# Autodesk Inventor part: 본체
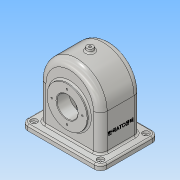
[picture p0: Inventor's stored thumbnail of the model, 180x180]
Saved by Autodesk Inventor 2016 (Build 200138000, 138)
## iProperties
Created: 2018-08
Part Number: 본체
Material: 알루미늄 6061
Document SubType Name: Modeling
Designer: Administrator
Density: 2.7 g/cm^3
Appearance: 알루미늄 - 평지
Mass: 1091.9 g
Surface Area: 1182.65 cm^2
Volume: 404.407 cm^3
Author: Administrator
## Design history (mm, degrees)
sketch "스케치1"
  geometry: L1 (-75, 55)-(75, 55); L2 (75, 55)-(75, -55); L3 (75, -55)-(-75, -55); L4 (-75, -55)-(-75, 55); L5 (-75, 55)-(75, -55); L6 (75, 55)-(-75, -55); 1 further point
  constraints: 12 end point, 2 midpoint, 2 parallel, 1 horizontal, 1 perpendicular
  dimensions: "d0" = 150 distance of L2.end L3.end; "d1" = 110 distance of L1.end L2.end
extrude "돌출1" new body sketch "스케치1" distance "d2" = 10; taper "d3" = 0 deg
sketch "스케치2"
  geometry: L1 (-75, 0)-(75, 0) reference; L2 (58, 78)-(58, 10); L3 (-75, 10)-(75, 10) reference; L4 (-58, 78)-(-58, 10); A1 r 58 centre (0, 78) between (58, 78) and (-58, 78); 2 further points
  constraints: 4 end point, 2 point on circle, 2 point on line, 1 centre point, 1 midpoint, 1 parallel, 1 tangent, 1 vertical, 1 vertical alignment
  dimensions: "d4" = 58 radius of A1; "d5" = 78 distance from line of L1 A1.centre; "d6" = 68 distance of L2.start L2.end
extrude "돌출2" join sketch "스케치2" stored distance "d7" = 77; taper "d8" = 0 deg
feature "쉘2" dims "d12" = 6, "d13" = 15, "d14" = 5
fillet "모깎기1" dims "d15" = 12
sketch "스케치3"
  geometry: L1 (63, 0)-(-63, 0) reference; C1 r 38 at (0, 65); 2 further points
  constraints: 1 centre point, 1 midpoint, 1 vertical alignment
  dimensions: "d17" = 76 diameter of C1; "d18" = 65 distance from line of L1 C1.centre
extrude "돌출3" join sketch "스케치3" distance "d19" = 5; taper "d20" = 0 deg
sketch "스케치4"
  geometry: L1 (-63, 0)-(63, 0) reference; C1 r 38 at (0, -65); 2 further points
  constraints: 1 centre point, 1 midpoint, 1 vertical alignment
  dimensions: "d21" = 76 diameter of C1; "d22" = 65 distance from line of L1 C1.centre
extrude "돌출4" join sketch "스케치4" distance "d23" = 10; taper "d24" = 0 deg
hole "구멍1" diameter "d36" = 40; stored, may be unused: countersink angle "d40" = 90 deg, drill point angle "d42" = 118 deg; dims "d34" = 10, "d35" = 10, "d37" = 6, "d38" = 4, "d39" = 2, "d41" = 8
sketch "스케치6"
  geometry: L1 (63, -65)-(-63, -65) reference; 3 further points
  constraints: 1 midpoint, 1 vertical alignment
  dimensions: "d43" = 94 distance from line of L1 point (0, 29)
hole "구멍2" sketch "스케치6" at (0, 29) diameter "d44" = 3.242; stored, may be unused: countersink angle "d48" = 90 deg, drill point angle "d50" = 118 deg; dims "d45" = 8, "d46" = 4, "d47" = 2, "d49" = 10
sketch "스케치7"
  geometry: L1 (-63, 65)-(63, 65) reference; 3 further points
  constraints: 1 midpoint, 1 vertical alignment
  dimensions: "d54" = 94 distance from line of L1 point (0, -29)
hole "구멍3" sketch "스케치7" at (0, -29) diameter "d55" = 3.242; stored, may be unused: countersink angle "d59" = 90 deg, drill point angle "d61" = 118 deg; dims "d56" = 8, "d57" = 4, "d58" = 2, "d60" = 10
fillet "모깎기2" dims "d65" = 13
sketch "스케치8"
  geometry: A1 r 12 centre (-63, -43) between (-75, -43) and (-63, -55) reference; 2 further points
  constraints: 1 coincident
hole "구멍4" sketch "스케치8" at (-63, -43) diameter "d66" = 5; stored, may be unused: countersink angle "d70" = 90 deg, drill point angle "d72" = 118 deg; dims "d67" = 20, "d68" = 12, "d69" = 4, "d71" = 10
fillet "모깎기3" dims "d73" = 8
node "작업 평면1"
sketch "스케치9"
  geometry: C1 r 6 at (0, 0); 1 further point
  constraints: 1 centre point, 1 coincident
  dimensions: "d75" = 12 diameter of C1
extrude "돌출5" join sketch "스케치9" stored distance "d76" = 10; taper "d77" = 5 deg
hole "구멍5" diameter "d80" = 4.459; stored, may be unused: countersink angle "d84" = 90 deg, drill point angle "d86" = 118 deg; dims "d78" = 10, "d79" = 10, "d81" = 25, "d82" = 12, "d83" = 4, "d85" = 12.8
sketch "스케치10"
  geometry: L1 (78, 68.5)-(78, -17.5) reference; L2 (0, -13)-(68, -13) reference; 2 further points
  constraints: 1 other
  dimensions: "d87" = 40 distance from line of L1 point (38, 25.5); "d88" = 38.5 distance from line of L2 point (38, 25.5)
feature "엠보싱1" sketch "스케치10" dims "d89" = 0.5, "d90" = 0
chamfer "모따기1" distance "d92" = 1; stored, may be unused: second distance "d93" = 2, angle "d94" = 45 deg
chamfer "모따기2" distance "d95" = 1; stored, may be unused: second distance "d96" = 2, angle "d97" = 45 deg
fillet "모깎기5" dims "d98" = 3
fillet "모깎기6" dims "d99" = 3
fillet "모깎기7" dims "d100" = 3
fillet "모깎기8" dims "d101" = 3
sketch "스케치11"
  geometry: L1 (-70.271, 65)-(73.342, 65); L2 (25.5, 0)-(-25.5, 0) reference; L3 (-43.5, 65)-(-19.5, 65); L4 (-19.5, 65)-(-19.5, 93); L5 (-19.5, 93)-(-33.5, 104.747); L6 (-33.5, 104.747)-(-33.5, 103); L7 (-33.5, 103)-(-43.5, 103); L8 (-43.5, 103)-(-43.5, 65); L9 (-43.5, 103)-(-43.5, 27) reference; 2 further points
  constraints: 14 end point, 3 horizontal, 2 perpendicular, 2 point on line, 1 midpoint, 1 parallel
  dimensions: "d107" = 65 distance between parallel lines of L2 L1; "d108" = 24 distance of L3.start L3.end; "d109" = 38 distance of L7.end L3.start; "d110" = 28 distance of L3.end L4.end; "d111" = 50 deg angle of L4 L5; "d112" = 10 distance of L6.end L7.end
revolve "회전2" sketch "스케치11" stored, may be unused: angle "d113" = 90 deg
sketch "스케치12"
  geometry: L1 (63, -65)-(-63, -65) reference; C1 r 20 at (0, 0); 2 further points
  constraints: 1 centre point, 1 coincident, 1 midpoint, 1 vertical alignment
  dimensions: "d115" = 40 diameter of C1; "d116" = 65 distance from line of L1 C1.centre
extrude "돌출6" cut sketch "스케치12" stored distance "d117" = 10; taper "d118" = 0 deg
chamfer "모따기3" distance "d119" = 1; stored, may be unused: second distance "d120" = 2, angle "d121" = 45 deg
sketch "스케치13"
  geometry: L1 (63, -65)-(-63, -65) reference; 3 further points
  constraints: 1 midpoint, 1 vertical alignment
  dimensions: "d122" = 94 distance from line of L1 point (0, 29)
hole "구멍6" sketch "스케치13" at (0, 29) diameter "d123" = 3.242; stored, may be unused: countersink angle "d127" = 90 deg, drill point angle "d129" = 118 deg; dims "d124" = 8, "d125" = 12, "d126" = 4, "d128" = 10
sketch "스케치14"
  geometry: L1 (0, -20.734)-(-100.286, -20.734); L2 (-100.286, -20.734)-(-100.286, 155.578); L3 (-100.286, 155.578)-(0, 155.578); L4 (0, 155.578)-(0, -20.734); 1 further point
  constraints: 8 end point, 2 parallel, 1 horizontal, 1 perpendicular
extrude "돌출7" cut sketch "스케치14" stored distance "d133" = 10; taper "d134" = 0 deg
node "솔리드1"
pattern_circular "원형 패턴2" dims angle "d63" = 360 deg
mirror "대칭1"
mirror "대칭2"
pattern_circular "원형 패턴3" dims angle "d131" = 360 deg
other parameters: "d74" = 142
